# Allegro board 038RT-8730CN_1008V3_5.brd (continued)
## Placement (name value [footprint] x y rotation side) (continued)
NOREF#506  -  []  315.1 202.13 90 top
NOREF#507  -  []  321.55 225.71 0 top
NOREF#508  -  []  179.95 285.03 90 top
NOREF#509  -  []  403.66 273.64 90 top
NOREF#510  -  []  334.22 259.67 0 top
NOREF#511  -  []  327.47 196.04 0 top
NOREF#512  -  []  334.33 132.51 90 top
NOREF#513  -  []  355.48 254.44 90 top
NOREF#514  -  []  198.23 208.86 90 top
NOREF#515  -  []  404.8 268.5 0 top
NOREF#516  -  []  316.16 262.17 90 top
NOREF#517  -  []  182.03 282.65 0 top
NOREF#518  -  []  290.97 245.28 0 top
NOREF#519  -  []  289.7 269.37 90 top
NOREF#520  -  []  454.13 176.57 90 top
NOREF#521  -  []  336.14 203.74 0 top
NOREF#522  -  []  288.29 251.82 0 top
NOREF#523  -  []  283.33 205.18 0 top
NOREF#524  -  []  426.14 176.74 0 top
NOREF#525  -  []  403.98 258.4 90 top
NOREF#526  -  []  254.37 167.31 0 top
NOREF#527  -  []  372.33 265.91 0 top
NOREF#528  -  []  275.6 192.3 90 top
NOREF#529  -  []  324.75 288.95 90 top
NOREF#530  -  []  256.93 288.03 90 top
NOREF#531  -  []  347.77 116.51 90 top
NOREF#532  -  []  405.68 185.52 90 top
NOREF#533  -  []  279.47 261.29 0 top
NOREF#534  -  []  364.5 184.96 0 top
NOREF#535  -  []  208.01 210.26 90 top
NOREF#536  -  []  258.58 279.62 90 top
NOREF#537  -  []  286.82 247.81 90 top
NOREF#538  -  []  299.3 254 90 top
NOREF#539  -  []  326.58 187.88 0 top
NOREF#540  -  []  311.98 81.48 0 top
NOREF#541  -  []  332.85 167.49 90 top
NOREF#542  -  []  497.31 228.11 90 top
NOREF#543  -  []  405.7 256.05 0 top
NOREF#544  -  []  219.02 298.37 90 top
NOREF#545  -  []  289.13 251.83 90 top
NOREF#546  -  []  292.38 288.89 0 top
NOREF#547  -  []  57.77 1.56 90 top
NOREF#548  -  []  292.38 198.4 0 top
NOREF#549  -  []  294.22 256.16 90 top
NOREF#550  -  []  452.5 83.49 0 top
NOREF#551  -  []  491.79 259.74 0 top
NOREF#552  -  []  313.36 166.49 90 top
NOREF#553  -  []  288.08 255.55 0 top
NOREF#554  -  []  364.8 244.64 0 top
NOREF#555  -  []  516.65 184.97 90 top
NOREF#556  -  []  491.79 251.1 0 top
NOREF#557  -  []  496.49 381.09 0 top
NOREF#558  -  []  293.33 257.12 0 top
NOREF#559  -  []  296.44 260.67 0 top
NOREF#560  -  []  261.58 297.69 90 top
NOREF#561  -  []  307.89 167.76 0 top
NOREF#562  -  []  364.8 195.09 90 top
NOREF#563  -  []  469.09 105.96 90 top
NOREF#564  -  []  284.5 184.96 0 top
NOREF#565  -  []  452.5 86.06 0 top
NOREF#566  -  []  166.06 132.93 0 top
NOREF#567  -  []  286.9 195.41 90 top
NOREF#568  -  []  466.61 364.96 90 top
NOREF#569  -  []  361.7 209.33 0 top
NOREF#570  -  []  412.72 265.56 0 top
NOREF#571  -  []  282.3 196.5 0 top
NOREF#572  -  []  264.41 233.58 0 top
NOREF#573  -  []  497.31 220.85 90 top
NOREF#574  -  []  333.29 120.91 0 top
NOREF#575  -  []  324.8 256.37 0 top
NOREF#576  -  []  405.76 200.49 90 top
NOREF#577  -  []  190.11 292.39 90 top
NOREF#578  -  []  408.66 191.82 0 top
NOREF#579  -  []  409.86 196.29 0 top
NOREF#580  -  []  445.07 181.97 0 top
NOREF#581  -  []  182.03 274.41 90 top
NOREF#582  -  []  361.57 262.44 90 top
NOREF#583  -  []  210.19 217.5 0 top
NOREF#584  -  []  494.38 377.23 0 top
NOREF#585  -  []  319.47 263.4 0 top
NOREF#586  -  []  295.96 70.62 90 top
NOREF#587  -  []  283.63 204.65 0 top
NOREF#588  -  []  320.37 209.76 0 top
NOREF#589  -  []  375.71 71.53 90 top
NOREF#590  -  []  348.53 136.15 0 top
NOREF#591  -  []  363.77 135.5 90 top
NOREF#592  -  []  332.38 228.89 0 top
NOREF#593  -  []  330.72 359.7 90 top
NOREF#594  -  []  52.77 68.06 0 top
NOREF#595  -  []  404.8 195.09 90 top
NOREF#596  -  []  311.47 80.68 90 top
NOREF#597  -  []  214.88 360.96 90 top
NOREF#598  -  []  412.01 301.38 0 top
NOREF#599  -  []  406.35 187.8 0 top
NOREF#600  -  []  320.37 269.76 0 top
NOREF#601  -  []  368.08 195.55 0 top
NOREF#602  -  []  275.6 192.3 90 top
NOREF#603  -  []  323.98 258.4 90 top
NOREF#604  -  []  408.17 95.22 90 top
NOREF#605  -  []  294.43 263.38 90 top
NOREF#606  -  []  334.33 121.95 0 top
NOREF#607  -  []  50.8 5 0 top
NOREF#608  -  []  292.17 189.51 90 top
NOREF#609  -  []  233.84 244.55 90 top
NOREF#610  -  []  314.28 208.98 90 top
NOREF#611  -  []  352.28 261.88 0 top
NOREF#612  -  []  326.57 255.72 0 top
NOREF#613  -  []  406.3 194.08 90 top
NOREF#614  -  []  453.02 182.02 90 top
NOREF#615  -  []  314.28 268.98 90 top
NOREF#616  -  []  451.91 302.69 0 top
NOREF#617  -  []  364.48 246.16 0 top
NOREF#618  -  []  316.86 69.01 90 top
NOREF#619  -  []  409.3 251.32 90 top
NOREF#620  -  []  324.8 184.64 0 top
NOREF#621  -  []  307.44 166.16 90 top
NOREF#622  -  []  35.96 348.27 90 top
NOREF#623  -  []  480.36 198.42 0 top
NOREF#624  -  []  399.47 200.61 0 top
NOREF#625  -  []  216.24 193.01 0 top
NOREF#626  -  []  324.48 246.16 0 top
NOREF#627  -  []  340.87 216.46 90 top
NOREF#628  -  []  403.63 265.5 0 top
NOREF#629  -  []  326.29 172.14 90 top
NOREF#630  -  []  520.87 166.68 90 top
NOREF#631  -  []  175.18 251.01 90 top
NOREF#632  -  []  478.56 170.21 90 top
NOREF#633  -  []  370.32 195.4 0 top
NOREF#634  -  []  280.89 191.48 90 top
NOREF#635  -  []  237.43 266.06 0 top
NOREF#636  -  []  342.85 246 45 top
NOREF#637  -  []  327.65 84.79 90 top
NOREF#638  -  []  320.21 173.54 90 top
NOREF#639  -  []  364.18 80.76 90 top
NOREF#640  -  []  283.37 196.69 0 top
NOREF#641  -  []  511.37 301.65 0 top
NOREF#642  -  []  326.4 227.56 90 top
NOREF#643  -  []  332.33 204.49 0 top
NOREF#644  -  []  347.77 131.75 90 top
NOREF#645  -  []  242.47 292.83 90 top
NOREF#646  -  []  369.7 209.37 90 top
NOREF#647  -  []  290.97 192.03 90 top
NOREF#648  -  []  289.86 256.29 0 top
NOREF#649  -  []  517.92 216.24 0 top
NOREF#650  -  []  290.35 250.17 0 top
NOREF#651  -  []  416.14 200.99 0 top
NOREF#652  -  []  329.29 255.34 90 top
NOREF#653  -  []  453.01 295.49 0 top
NOREF#654  -  []  324.75 218.11 90 top
NOREF#655  -  []  319.47 259.92 0 top
NOREF#656  -  []  521.42 276.57 90 top
NOREF#657  -  []  421.05 295.32 0 top
NOREF#658  -  []  384.41 123.59 0 top
NOREF#659  -  []  338.02 169.36 0 top
NOREF#660  -  []  413.03 273.89 0 top
NOREF#661  -  []  368.54 191.43 0 top
NOREF#662  -  []  268.75 79.79 0 top
NOREF#663  -  []  219.44 218.9 90 top
NOREF#664  -  []  415.29 178.14 0 top
NOREF#665  -  []  52.77 6.56 0 top
NOREF#666  -  []  188.98 203 0 top
NOREF#667  -  []  334.67 251.62 90 top
NOREF#668  -  []  325.7 244.32 90 top
NOREF#669  -  []  242.32 174.51 0 top
NOREF#670  -  []  321.57 199.65 90 top
NOREF#671  -  []  321.21 252.38 0 top
NOREF#672  -  []  181.48 258.99 90 top
NOREF#673  -  []  363.13 294.52 0 top
NOREF#674  -  []  284.8 255.09 90 top
NOREF#675  -  []  507.05 334.96 0 top
NOREF#676  -  []  500.02 182.52 0 top
NOREF#677  -  []  363.61 152.59 0 top
NOREF#678  -  []  193.38 287.48 0 top
NOREF#679  -  []  433.26 348.24 0 top
NOREF#680  -  []  333.92 264.92 90 top
NOREF#681  -  []  52.77 6.56 0 top
NOREF#682  -  []  404.5 184.96 0 top
NOREF#683  -  []  415.42 259.88 90 top
NOREF#684  -  []  182.03 194.4 90 top
NOREF#685  -  []  191.18 175.97 0 top
NOREF#686  -  []  370.07 190.47 0 top
NOREF#687  -  []  210.19 191.61 0 top
NOREF#688  -  []  500.02 267 0 top
NOREF#689  -  []  365.7 207.17 0 top
NOREF#690  -  []  204.81 193.01 0 top
NOREF#691  -  []  365.3 262 0 top
NOREF#692  -  []  491.79 191.16 0 top
NOREF#693  -  []  414.43 261.87 90 top
NOREF#694  -  []  326.9 200.19 0 top
NOREF#695  -  []  333.02 256.8 0 top
NOREF#696  -  []  345.45 295.32 0 top
NOREF#697  -  []  423.36 169.36 0 top
NOREF#698  -  []  410.76 255.38 0 top
NOREF#699  -  []  328.67 195.4 90 top
NOREF#700  -  []  510.1 154.21 0 top
NOREF#701  -  []  259.15 90.74 0 top
NOREF#702  -  []  253.73 185.16 0 top
NOREF#703  -  []  373.23 266.23 0 top
NOREF#704  -  []  357.15 228.96 0 top
NOREF#705  -  []  406.58 187.42 0 top
NOREF#706  -  []  292.72 205.56 0 top
NOREF#707  -  []  337.4 96.1 0 top
NOREF#708  -  []  404.8 244.64 0 top
NOREF#709  -  []  31.6 377.83 0 top
NOREF#710  -  []  295.42 259.03 90 top
NOREF#711  -  []  511.9 245.66 90 top
NOREF#712  -  []  336.44 263.42 0 top
NOREF#713  -  []  503.22 182.52 0 top
NOREF#714  -  []  466.31 234.11 0 top
NOREF#715  -  []  287.13 84.79 90 top
NOREF#716  -  []  28.17 358.15 0 top
NOREF#717  -  []  325.7 186.14 90 top
NOREF#718  -  []  398.83 207.9 90 top
NOREF#719  -  []  251.53 212.44 0 top
NOREF#720  -  []  367.56 270 0 top
NOREF#721  -  []  465.96 232.71 0 top
NOREF#722  -  []  328.41 200.19 0 top
NOREF#723  -  []  208.01 184.61 90 top
NOREF#724  -  []  458.33 238.23 90 top
NOREF#725  -  []  400.37 203.08 0 top
NOREF#726  -  []  55.8 0 90 top
NOREF#727  -  []  318.02 79.81 0 top
NOREF#728  -  []  296.14 263.74 0 top
NOREF#729  -  []  640.8 0 90 top
NOREF#730  -  []  450.62 271.89 0 top
NOREF#731  -  []  478.8 446.5 0 top
NOREF#732  -  []  308.3 285 0 top
NOREF#733  -  []  514.57 298.46 90 top
NOREF#734  -  []  493.99 191.16 0 top
NOREF#735  -  []  370.97 252.03 90 top
NOREF#736  -  []  315.5 227.56 0 top
NOREF#737  -  []  514.57 259.77 90 top
NOREF#738  -  []  283.05 255.79 90 top
NOREF#739  -  []  253.73 274.01 0 top
NOREF#740  -  []  318.05 151.39 0 top
NOREF#741  -  []  279.47 263.4 0 top
NOREF#742  -  []  214.04 175.97 0 top
NOREF#743  -  []  338.23 89.67 0 top
NOREF#744  -  []  421.41 170.34 90 top
NOREF#745  -  []  370.97 192.03 90 top
NOREF#746  -  []  291.52 254.76 90 top
NOREF#747  -  []  491.79 267 0 top
NOREF#748  -  []  208.01 175.97 90 top
NOREF#749  -  []  471.17 382.58 0 top
NOREF#750  -  []  406.35 247.8 0 top
NOREF#751  -  []  198.23 217.5 90 top
NOREF#752  -  []  284.48 246.16 0 top
NOREF#753  -  []  366.58 200.49 90 top
NOREF#754  -  []  323.33 265.18 0 top
NOREF#755  -  []  227.42 83.32 0 top
NOREF#756  -  []  245.98 198.11 0 top
NOREF#757  -  []  300.53 204.49 0 top
NOREF#758  -  []  344.74 75.65 90 top
NOREF#759  -  []  356.8 45.5 0 top
NOREF#760  -  []  218.95 295.5 90 top
NOREF#761  -  []  327.82 269.36 90 top
NOREF#762  -  []  514.57 261.96 90 top
NOREF#763  -  []  253.3 324 0 top
NOREF#764  -  []  376.14 203.74 0 top
NOREF#765  -  []  408.09 259.55 90 top
NOREF#766  -  []  521.42 242.28 90 top
NOREF#767  -  []  471.13 208.41 0 top
NOREF#768  -  []  348.3 285 0 top
NOREF#769  -  []  321.57 198.96 90 top
NOREF#770  -  []  287.88 209.1 90 top
NOREF#771  -  []  344.47 167.76 0 top
NOREF#772  -  []  314.08 260.75 0 top
NOREF#773  -  []  27.57 380.69 90 top
NOREF#774  -  []  205.34 106.22 90 top
NOREF#775  -  []  353.33 201.92 0 top
NOREF#776  -  []  281.55 285.71 0 top
NOREF#777  -  []  363.77 118.31 90 top
NOREF#778  -  []  266.21 296.8 90 top
NOREF#779  -  []  284.1 199 0 top
NOREF#780  -  []  488.59 263.8 90 top
NOREF#781  -  []  317.29 137.95 0 top
NOREF#782  -  []  225.47 295.88 0 top
NOREF#783  -  []  367.93 244.02 90 top
NOREF#784  -  []  369.3 191.32 90 top
NOREF#785  -  []  366.35 247.8 0 top
NOREF#786  -  []  262.58 350.14 0 top
NOREF#787  -  []  243.59 208.8 90 top
NOREF#788  -  []  333.02 197.65 0 top
NOREF#789  -  []  420.81 266.84 90 top
NOREF#790  -  []  373.36 190.09 0 top
NOREF#791  -  []  260.06 383.9 90 top
NOREF#792  -  []  466.31 286.79 0 top
NOREF#793  -  []  452.86 93.57 90 top
NOREF#794  -  []  409.71 195.72 90 top
NOREF#795  -  []  413.3 197.5 90 top
NOREF#796  -  []  315.6 252.3 90 top
NOREF#797  -  []  514.57 241.31 90 top
NOREF#798  -  []  323.33 204.33 0 top
NOREF#799  -  []  33.88 370.85 0 top
NOREF#800  -  []  450.39 84.76 0 top
NOREF#801  -  []  366.23 247.42 0 top
NOREF#802  -  []  414.73 172.88 0 top
NOREF#803  -  []  409.35 210.01 0 top
NOREF#804  -  []  520.87 246.69 90 top
NOREF#805  -  []  349.3 246 90 top
NOREF#806  -  []  349.18 256.09 90 top
NOREF#807  -  []  383.3 220 0 top
NOREF#808  -  []  188.31 191.57 90 top
NOREF#809  -  []  380.3 197 90 top
NOREF#810  -  []  389.18 258.29 90 top
NOREF#811  -  []  369.13 251.83 90 top
NOREF#812  -  []  221.09 167.31 90 top
NOREF#813  -  []  313.93 102.82 0 top
NOREF#814  -  []  365.68 245.52 90 top
NOREF#815  -  []  289.11 191.32 90 top
NOREF#816  -  []  232.16 300.68 0 top
NOREF#817  -  []  364.54 212.7 90 top
NOREF#818  -  []  293.23 267.72 0 top
NOREF#819  -  []  516.65 207.83 90 top
NOREF#820  -  []  333.03 273.89 0 top
NOREF#821  -  []  277 290.7 90 top
NOREF#822  -  []  408.89 251.89 0 top
NOREF#823  -  []  293.23 264.02 0 top
NOREF#824  -  []  211.84 168.71 0 top
NOREF#825  -  []  326.08 200.19 0 top
NOREF#826  -  []  465.73 208.41 0 top
NOREF#827  -  []  521.42 162.27 90 top
NOREF#828  -  []  331.55 189.53 90 top
NOREF#829  -  []  282.3 196.5 0 top
NOREF#830  -  []  339.43 227.49 90 top
NOREF#831  -  []  374.43 201.87 90 top
NOREF#832  -  []  557.05 87.46 0 top
NOREF#833  -  []  289.66 255.8 90 top
NOREF#834  -  []  429.34 176.74 0 top
NOREF#835  -  []  405.1 254.72 0 top
NOREF#836  -  []  413.23 266.23 0 top
NOREF#837  -  []  188.98 175.97 0 top
NOREF#838  -  []  406.29 172.14 90 top
NOREF#839  -  []  494.38 379.8 0 top
NOREF#840  -  []  253.73 288.03 0 top
NOREF#841  -  []  240.78 254.09 0 top
NOREF#842  -  []  405.98 247.8 0 top
NOREF#843  -  []  195.73 224.34 90 top
NOREF#844  -  []  414.57 218.11 90 top
NOREF#845  -  []  511.37 175.92 0 top
NOREF#846  -  []  409.7 176.75 0 top
NOREF#847  -  []  414.22 260.52 0 top
NOREF#848  -  []  245.98 266.69 0 top
NOREF#849  -  []  489.17 295.43 0 top
NOREF#850  -  []  288.5 210.01 0 top
NOREF#851  -  []  220.09 291.05 90 top
NOREF#852  -  []  24.62 412.09 90 top
NOREF#853  -  []  215.43 367.16 90 top
NOREF#854  -  []  332.72 265.56 0 top
NOREF#855  -  []  500.56 80.76 90 top
NOREF#856  -  []  430.7 167.76 0 top
NOREF#857  -  []  368.89 191.43 0 top
NOREF#858  -  []  376.63 169.36 0 top
NOREF#859  -  []  198.23 201.6 90 top
NOREF#860  -  []  277.15 228.96 0 top
NOREF#861  -  []  273.3 180 90 top
NOREF#862  -  []  404.8 247.74 90 top
NOREF#863  -  []  294.22 197.01 90 top
NOREF#864  -  []  181.48 293.28 90 top
NOREF#865  -  []  401.57 201.78 90 top
NOREF#866  -  []  414.22 197.01 90 top
NOREF#867  -  []  325.97 193.75 0 top
NOREF#868  -  []  276.62 97.42 90 top
NOREF#869  -  []  274.28 268.98 90 top
NOREF#870  -  []  322.9 269.33 0 top
NOREF#871  -  []  292.7 250.29 0 top
NOREF#872  -  []  228.44 278.84 0 top
NOREF#873  -  []  321.8 297.54 0 top
NOREF#874  -  []  374.43 203.38 90 top
NOREF#875  -  []  513.7 222.79 90 top
NOREF#876  -  []  211.84 193.01 0 top
NOREF#877  -  []  282.2 269.75 0 top
NOREF#878  -  []  271.3 222 0 top
NOREF#879  -  []  326.8 247.3 90 top
NOREF#880  -  []  192.73 292.39 0 top
NOREF#881  -  []  218.13 108.35 90 top
NOREF#882  -  []  331.05 276.46 90 top
NOREF#883  -  []  414.57 282.51 90 top
NOREF#884  -  []  368.24 298.51 90 top
NOREF#885  -  []  175.18 171 90 top
NOREF#886  -  []  521.42 293.5 0 top
NOREF#887  -  []  408.46 196.44 0 top
NOREF#888  -  []  330.67 191.75 90 top
NOREF#889  -  []  326.82 187.81 90 top
NOREF#890  -  []  414.12 294.95 0 top
NOREF#891  -  []  421.41 167.75 90 top
NOREF#892  -  []  364.8 255.09 90 top
NOREF#893  -  []  336.24 259.17 0 top
NOREF#894  -  []  276.1 286.51 0 top
NOREF#895  -  []  363.33 204.33 0 top
NOREF#896  -  []  206.37 333.52 0 top
NOREF#897  -  []  471.13 216.81 0 top
NOREF#898  -  []  319.69 298.81 0 top
NOREF#899  -  []  286.4 287.55 90 top
NOREF#900  -  []  328.76 209.36 90 top
NOREF#901  -  []  414.11 88.62 0 top
NOREF#902  -  []  520.87 200.97 90 top
NOREF#903  -  []  376.44 260.67 0 top
NOREF#904  -  []  381.05 295.32 0 top
NOREF#905  -  []  319.09 137.19 0 top
NOREF#906  -  []  409.34 186.99 0 top
NOREF#907  -  []  356.16 202.17 90 top
NOREF#908  -  []  407.88 209.1 90 top
NOREF#909  -  []  403.33 204.33 0 top
NOREF#910  -  []  375.71 72.8 90 top
NOREF#911  -  []  198.61 118.51 0 top
NOREF#912  -  []  413.83 246.93 0 top
NOREF#913  -  []  209.66 167.31 90 top
NOREF#914  -  []  50.8 465 0 top
NOREF#915  -  []  400.37 260.29 0 top
NOREF#916  -  []  289.3 191.32 90 top
NOREF#917  -  []  200.41 193.01 0 top
NOREF#918  -  []  403.98 259.6 90 top
NOREF#919  -  []  293.23 202.51 0 top
NOREF#920  -  []  284.75 220.31 90 top
NOREF#921  -  []  516.65 191.02 0 top
NOREF#922  -  []  364.1 199 0 top
NOREF#923  -  []  409.66 195.8 90 top
NOREF#924  -  []  332.19 192 90 top
NOREF#925  -  []  351.84 169.66 0 top
NOREF#926  -  []  516.65 242.12 90 top
NOREF#927  -  []  287.36 200.49 90 top
NOREF#928  -  []  281.8 300.11 0 top
NOREF#929  -  []  405.7 267.17 0 top
NOREF#930  -  []  226.93 241.49 90 top
NOREF#931  -  []  282.56 83.49 0 top
NOREF#932  -  []  482.56 216.81 0 top
NOREF#933  -  []  404.75 282.51 90 top
NOREF#934  -  []  369.61 259.55 90 top
NOREF#935  -  []  496.49 381.09 0 top
NOREF#936  -  []  309.18 258.29 90 top
NOREF#937  -  []  187.33 217.5 0 top
NOREF#938  -  []  326.33 195.34 90 top
NOREF#939  -  []  224.59 243.15 0 top
NOREF#940  -  []  462.76 263.8 90 top
NOREF#941  -  []  -18.78 412.09 0 top
NOREF#942  -  []  482.91 220.85 90 top
NOREF#943  -  []  451.91 192.56 0 top
NOREF#944  -  []  188.98 271.58 0 top
NOREF#945  -  []  279.47 210.08 0 top
NOREF#946  -  []  409.3 251.52 90 top
NOREF#947  -  []  238.62 264.79 0 top
NOREF#948  -  []  309.18 260.49 90 top
NOREF#949  -  []  328.09 255.99 0 top
NOREF#950  -  []  391.08 208.98 0 top
NOREF#951  -  []  440.51 229.39 90 top
NOREF#952  -  []  369.77 192.68 0 top
NOREF#953  -  []  288.3 265 0 top
NOREF#954  -  []  182.03 191.21 90 top
NOREF#955  -  []  383.61 122.32 0 top
NOREF#956  -  []  244.11 263.52 90 top
NOREF#957  -  []  216.24 218.9 0 top
NOREF#958  -  []  305.76 344.61 90 top
NOREF#959  -  []  290.97 190.15 0 top
NOREF#960  -  []  505.92 222.45 0 top
NOREF#961  -  []  246.78 226.6 0 top
NOREF#962  -  []  239.54 230.5 0 top
NOREF#963  -  []  221.09 251.79 90 top
NOREF#964  -  []  412.33 207.4 0 top
NOREF#965  -  []  294.73 170.29 0 top
NOREF#966  -  []  477.16 247.91 90 top
NOREF#967  -  []  516.65 253.55 90 top
NOREF#968  -  []  359.47 270.08 0 top
NOREF#969  -  []  229.35 382.58 90 top
NOREF#970  -  []  333.32 197.97 0 top
NOREF#971  -  []  364.81 121.95 0 top
NOREF#972  -  []  337.33 87.58 0 top
NOREF#973  -  []  360.37 200.97 0 top
NOREF#974  -  []  385.98 263.69 0 top
NOREF#975  -  []  281.7 269.33 0 top
NOREF#976  -  []  309.18 196.09 90 top
NOREF#977  -  []  200.41 271.58 0 top
NOREF#978  -  []  319.69 301.38 0 top
NOREF#979  -  []  389.34 243.1 0 top
NOREF#980  -  []  326.82 247.81 90 top
NOREF#981  -  []  334.5 189.29 90 top
NOREF#982  -  []  57.77 1.56 90 top
NOREF#983  -  []  269.18 200.49 90 top
NOREF#984  -  []  333.13 147.59 90 top
NOREF#985  -  []  52.77 6.56 0 top
NOREF#986  -  []  246.78 295.18 0 top
NOREF#987  -  []  328.67 255.4 90 top
NOREF#988  -  []  477.16 232.71 0 top
NOREF#989  -  []  320.37 260.29 0 top
NOREF#990  -  []  514.57 227.67 90 top
NOREF#991  -  []  175.18 182.43 90 top
NOREF#992  -  []  520.17 212.21 90 top
NOREF#993  -  []  329.86 256.29 0 top
NOREF#994  -  []  373.23 264.02 0 top
NOREF#995  -  []  431.03 189.48 0 top
NOREF#996  -  []  404.8 246.46 0 top
NOREF#997  -  []  155.68 219.47 0 top
NOREF#998  -  []  286.9 256.05 90 top
NOREF#999  -  []  286.37 293.68 90 top
NOREF#1000  -  []  336.48 126.78 90 top
NOREF#1001  -  []  369.29 195.34 90 top
NOREF#1002  -  []  406.3 193.44 90 top
NOREF#1003  -  []  468.93 251.1 0 top
NOREF#1004  -  []  457.37 381.09 0 top
NOREF#1005  -  []  353.3 290 0 top
NOREF#1006  -  []  200.41 253.19 0 top
NOREF#1007  -  []  326.99 247.5 90 top
NOREF#1008  -  []  500.02 247.91 90 top
NOREF#1009  -  []  179.95 302.51 0 top
NOREF#1010  -  []  367.08 257.69 0 top
NOREF#1011  -  []  213.15 378.53 0 top
NOREF#1012  -  []  461.95 377.26 90 top
NOREF#1013  -  []  282.04 74.78 0 top
NOREF#1014  -  []  368.46 196.44 0 top
NOREF#1015  -  []  288.09 260.49 90 top
NOREF#1016  -  []  368.07 193.43 90 top
NOREF#1017  -  []  439.67 291.85 0 top
NOREF#1018  -  []  347.77 137.95 0 top
NOREF#1019  -  []  289.82 246.49 0 top
NOREF#1020  -  []  361.55 228.96 0 top
NOREF#1021  -  []  292.17 244.64 90 top
NOREF#1022  -  []  204.81 175.97 0 top
NOREF#1023  -  []  369.67 269.11 90 top
NOREF#1024  -  []  405.76 260.49 90 top
NOREF#1025  -  []  330.97 252.03 90 top
NOREF#1026  -  []  186.51 292.39 0 top
NOREF#1027  -  []  505.92 302.46 0 top
NOREF#1028  -  []  175.18 205.29 90 top
NOREF#1029  -  []  381.07 138.01 0 top
NOREF#1030  -  []  363.33 264.33 0 top
NOREF#1031  -  []  288.89 191.89 0 top
NOREF#1032  -  []  369.61 199.55 90 top
NOREF#1033  -  []  262.58 335.72 0 top
NOREF#1034  -  []  363.34 273.34 0 top
NOREF#1035  -  []  364.8 245.52 0 top
NOREF#1036  -  []  482.91 255.14 90 top
NOREF#1037  -  []  219.02 229.79 90 top
NOREF#1038  -  []  356.79 294.51 0 top
NOREF#1039  -  []  411.14 185.99 90 top
NOREF#1040  -  []  211.84 271.58 0 top
NOREF#1041  -  []  363.05 195.79 90 top
NOREF#1042  -  []  406.94 209.1 90 top
NOREF#1043  -  []  287.59 256.03 0 top
NOREF#1044  -  []  500.02 222.25 90 top
NOREF#1045  -  []  374.22 256.16 90 top
NOREF#1046  -  []  212.27 298.04 0 top
NOREF#1047  -  []  275.93 267.58 90 top
NOREF#1048  -  []  52.77 405.06 0 top
NOREF#1049  -  []  155.68 265.19 0 top
NOREF#1050  -  []  369.86 256.29 0 top
NOREF#1051  -  []  246.78 260.89 0 top
NOREF#1052  -  []  323.07 83.49 0 top
NOREF#1053  -  []  221.62 217.5 0 top
NOREF#1054  -  []  328.09 260.49 90 top
NOREF#1055  -  []  503.22 216.81 0 top
NOREF#1056  -  []  355.6 192.3 90 top
NOREF#1057  -  []  462.76 301.29 0 top
NOREF#1058  -  []  355.93 207.58 90 top
NOREF#1059  -  []  286.3 194.08 90 top
NOREF#1060  -  []  327.65 87.35 90 top
NOREF#1061  -  []  208.01 244.55 90 top
NOREF#1062  -  []  283.05 195.79 90 top
NOREF#1063  -  []  175.18 239.58 90 top
NOREF#1064  -  []  429.69 187.88 90 top
NOREF#1065  -  []  412.72 205.56 0 top
NOREF#1066  -  []  493.99 294.03 0 top
NOREF#1067  -  []  253.99 305.54 0 top
NOREF#1068  -  []  330.32 255.4 0 top
NOREF#1069  -  []  195.27 118.51 0 top
NOREF#1070  -  []  216.24 184.61 0 top
NOREF#1071  -  []  368.76 209.36 90 top
NOREF#1072  -  []  477.16 259.74 0 top
NOREF#1073  -  []  408.53 287.49 0 top
NOREF#1074  -  []  491.79 216.81 0 top
NOREF#1075  -  []  480.36 276.99 0 top
NOREF#1076  -  []  396.25 297.68 90 top
NOREF#1077  -  []  414.42 264.17 90 top
NOREF#1078  -  []  400.35 208.16 90 top
NOREF#1079  -  []  450.62 237.6 0 top
NOREF#1080  -  []  500.02 301.29 0 top
NOREF#1081  -  []  427.3 136.36 0 top
NOREF#1082  -  []  480.36 216.81 0 top
NOREF#1083  -  []  363.61 117.11 90 top
NOREF#1084  -  []  416.44 260.67 0 top
NOREF#1085  -  []  188.98 218.9 0 top
NOREF#1086  -  []  214.04 244.55 0 top
NOREF#1087  -  []  385.45 295.32 0 top
NOREF#1088  -  []  466.31 218.21 0 top
NOREF#1089  -  []  284.8 255.09 90 top
NOREF#1090  -  []  240.95 223.95 0 top
NOREF#1091  -  []  326.13 245.02 0 top
NOREF#1092  -  []  368.56 254.22 0 top
NOREF#1093  -  []  266.68 208.98 0 top
NOREF#1094  -  []  331.82 265.24 0 top
NOREF#1095  -  []  366.35 187.8 0 top
NOREF#1096  -  []  363.77 148.79 90 top
NOREF#1097  -  []  408.89 191.43 0 top
NOREF#1098  -  []  289.08 127.05 90 top
NOREF#1099  -  []  275.6 300.87 0 top
NOREF#1100  -  []  328.28 257.05 90 top
NOREF#1101  -  []  283.59 97.42 90 top
NOREF#1102  -  []  280.37 263.08 0 top
NOREF#1103  -  []  330.97 185.28 0 top
NOREF#1104  -  []  329.87 256.73 0 top
NOREF#1105  -  []  26.52 339.1 0 top
NOREF#1106  -  []  175.18 262.44 90 top
NOREF#1107  -  []  328.28 197.05 90 top
NOREF#1108  -  []  366.3 253.44 90 top
NOREF#1109  -  []  55.8 0 90 top
NOREF#1110  -  []  369.13 191.83 90 top
NOREF#1111  -  []  238.16 263.19 90 top
NOREF#1112  -  []  372.38 198.4 0 top
NOREF#1113  -  []  361.57 202.44 90 top
NOREF#1114  -  []  279.47 200.61 0 top
NOREF#1115  -  []  485.88 212.21 90 top
NOREF#1116  -  []  414.67 191.62 90 top
NOREF#1117  -  []  328.89 251.43 0 top
NOREF#1118  -  []  297.34 263.1 90 top
NOREF#1119  -  []  465.73 247.91 90 top
NOREF#1120  -  []  375.29 178.14 0 top
NOREF#1121  -  []  404.1 259 0 top
NOREF#1122  -  []  222.8 45.5 0 top
NOREF#1123  -  []  439.67 247.35 90 top
NOREF#1124  -  []  285.13 188.64 0 top
NOREF#1125  -  []  249.33 212.44 0 top
NOREF#1126  -  []  332.33 207.4 0 top
NOREF#1127  -  []  505.92 188.16 0 top
NOREF#1128  -  []  328.09 200.49 90 top
NOREF#1129  -  []  347.24 75.38 90 top
NOREF#1130  -  []  329.31 191.57 90 top
NOREF#1131  -  []  230.64 210.26 0 top
NOREF#1132  -  []  282.9 369.19 0 top
NOREF#1133  -  []  366.99 187.5 90 top
NOREF#1134  -  []  288.1 259.55 90 top
NOREF#1135  -  []  482.91 289.43 90 top
NOREF#1136  -  []  50.8 5 0 top
NOREF#1137  -  []  320.35 268.16 90 top
NOREF#1138  -  []  332.19 252 90 top
NOREF#1139  -  []  339.37 97.97 0 top
NOREF#1140  -  []  493.99 174.12 0 top
NOREF#1141  -  []  488.59 191.16 0 top
NOREF#1142  -  []  295.13 272.93 90 top
NOREF#1143  -  []  208.01 227.3 90 top
NOREF#1144  -  []  182.03 202.64 0 top
NOREF#1145  -  []  287.82 269.36 90 top
NOREF#1146  -  []  355.48 194.44 90 top
NOREF#1147  -  []  505.42 191.16 0 top
NOREF#1148  -  []  256.93 212.44 90 top
NOREF#1149  -  []  491.79 182.52 0 top
NOREF#1150  -  []  50.8 465 0 top
NOREF#1151  -  []  414.22 200.52 0 top
NOREF#1152  -  []  364.8 187.74 90 top
NOREF#1153  -  []  507.47 188.5 90 top
NOREF#1154  -  []  336.28 121.95 0 top
NOREF#1155  -  []  202.61 218.9 0 top
NOREF#1156  -  []  263.3 280 0 top
NOREF#1157  -  []  296.14 200.99 0 top
NOREF#1158  -  []  243.59 243.09 90 top
NOREF#1159  -  []  286.33 195.34 90 top
NOREF#1160  -  []  465.73 216.81 0 top
NOREF#1161  -  []  476.96 97.33 90 top
NOREF#1162  -  []  320.21 169.14 90 top
NOREF#1163  -  []  230.87 287.48 90 top
NOREF#1164  -  []  365.2 77.1 0 top
NOREF#1165  -  []  368.41 200.19 0 top
NOREF#1166  -  []  373.02 197.65 0 top
NOREF#1167  -  []  198.76 277.44 0 top
NOREF#1168  -  []  333.47 252.26 0 top
NOREF#1169  -  []  321.55 288.95 0 top
NOREF#1170  -  []  187.11 224.34 0 top
NOREF#1171  -  []  333.32 199.35 0 top
NOREF#1172  -  []  439.67 216.26 0 top
NOREF#1173  -  []  286.62 270 0 top
NOREF#1174  -  []  274.08 200.75 0 top
NOREF#1175  -  []  334.43 204.17 90 top
NOREF#1176  -  []  493.99 225.45 0 top
NOREF#1177  -  []  323.66 213.64 90 top
NOREF#1178  -  []  408.08 255.55 0 top
NOREF#1179  -  []  288.46 196.44 0 top
NOREF#1180  -  []  488.59 229.51 90 top
NOREF#1181  -  []  450.39 228.51 90 top
NOREF#1182  -  []  375.42 199.88 90 top
NOREF#1183  -  []  311.08 268.98 0 top
NOREF#1184  -  []  401.57 200.33 90 top
NOREF#1185  -  []  407.36 260.49 90 top
NOREF#1186  -  []  370.97 185.28 0 top
NOREF#1187  -  []  285.3 267 90 top
NOREF#1188  -  []  434.35 278.29 90 top
NOREF#1189  -  []  179.95 211.07 0 top
NOREF#1190  -  []  410.3 263 90 top
NOREF#1191  -  []  316.86 75.11 90 top
NOREF#1192  -  []  227.67 261.59 0 top
NOREF#1193  -  []  216.24 261.59 0 top
NOREF#1194  -  []  291.37 285.71 0 top
NOREF#1195  -  []  214.04 271.58 0 top
NOREF#1196  -  []  326.58 247.88 0 top
NOREF#1197  -  []  291.55 249.53 90 top
NOREF#1198  -  []  461.95 377.26 90 top
NOREF#1199  -  []  179.95 182.16 90 top
NOREF#1200  -  []  337.34 204.47 90 top
NOREF#1201  -  []  55.8 0 90 top
NOREF#1202  -  []  334.5 249.29 90 top
NOREF#1203  -  []  367 247.55 90 top
NOREF#1204  -  []  325.7 256.05 0 top
NOREF#1205  -  []  366.3 193.44 90 top
NOREF#1206  -  []  503.22 294.03 0 top
NOREF#1207  -  []  416.84 171.61 0 top
NOREF#1208  -  []  508.74 238.1 90 top
NOREF#1209  -  []  351.72 142.02 90 top
NOREF#1210  -  []  231.15 359.7 90 top
NOREF#1211  -  []  368.67 195.4 90 top
NOREF#1212  -  []  399.47 270.08 0 top
NOREF#1213  -  []  429.81 167.76 0 top
NOREF#1214  -  []  283.63 264.65 0 top
NOREF#1215  -  []  405.13 248.64 0 top
NOREF#1216  -  []  426.14 183.1 0 top
NOREF#1217  -  []  329.61 199.55 90 top
NOREF#1218  -  []  268.3 225 0 top
NOREF#1219  -  []  364.8 247.74 90 top
NOREF#1220  -  []  293.33 259.35 0 top
NOREF#1221  -  []  354.08 260.75 0 top
NOREF#1222  -  []  505.73 361.76 90 top
NOREF#1223  -  []  285.13 248.64 0 top
NOREF#1224  -  []  406.9 195.41 90 top
NOREF#1225  -  []  368.28 197.05 90 top
NOREF#1226  -  []  482.91 296.69 90 top
NOREF#1227  -  []  520.17 280.79 90 top
NOREF#1228  -  []  315.93 267.58 90 top
NOREF#1229  -  []  290.76 255.38 0 top
NOREF#1230  -  []  521.42 253.71 90 top
NOREF#1231  -  []  355.33 296.48 90 top
NOREF#1232  -  []  422.85 246 45 top
NOREF#1233  -  []  364.8 196.37 0 top
NOREF#1234  -  []  220.09 222.47 90 top
NOREF#1235  -  []  366.96 126.78 90 top
NOREF#1236  -  []  465.73 182.52 0 top
NOREF#1237  -  []  379.2 167.5 90 top
NOREF#1238  -  []  57.77 1.56 90 top
NOREF#1239  -  []  514.57 181.95 90 top
NOREF#1240  -  []  410.9 262.85 90 top
NOREF#1241  -  []  287.56 210 0 top
NOREF#1242  -  []  386.5 93.18 0 top
NOREF#1243  -  []  497.31 272.39 90 top
NOREF#1244  -  []  497.31 193.82 90 top
NOREF#1245  -  []  516.65 225.31 0 top
NOREF#1246  -  []  314.45 360.96 90 top
NOREF#1247  -  []  326.37 293.68 90 top
NOREF#1248  -  []  221.62 225.9 0 top
NOREF#1249  -  []  462.76 222.25 90 top
NOREF#1250  -  []  326.62 210 0 top
NOREF#1251  -  []  278.83 267.9 90 top
NOREF#1252  -  []  317.15 288.95 0 top
NOREF#1253  -  []  380.81 266.84 90 top
NOREF#1254  -  []  362.41 191.74 90 top
NOREF#1255  -  []  383.3 190 90 top
NOREF#1256  -  []  232.52 217.5 90 top
NOREF#1257  -  []  399.47 199.92 0 top
NOREF#1258  -  []  488.59 239.5 90 top
NOREF#1259  -  []  380.3 257 90 top
NOREF#1260  -  []  397.15 288.95 0 top
NOREF#1261  -  []  414.47 93.57 90 top
NOREF#1262  -  []  445.07 188.98 0 top
NOREF#1263  -  []  202.61 295.88 0 top
NOREF#1264  -  []  406.3 254.08 90 top
NOREF#1265  -  []  428.82 286.24 0 top
NOREF#1266  -  []  270.8 45.5 0 top
NOREF#1267  -  []  435.12 225.37 90 top
NOREF#1268  -  []  513.7 154.21 90 top
NOREF#1269  -  []  404.54 272.7 90 top
NOREF#1270  -  []  333.29 135.5 90 top
NOREF#1271  -  []  294.43 267.08 90 top
NOREF#1272  -  []  221.62 260.19 0 top
NOREF#1273  -  []  282.9 269.33 0 top
NOREF#1274  -  []  459.51 199.5 90 top
NOREF#1275  -  []  335.13 272.93 90 top
NOREF#1276  -  []  279.69 298.81 0 top
NOREF#1277  -  []  465.96 259.74 0 top
NOREF#1278  -  []  477.16 195.22 90 top
NOREF#1279  -  []  405.3 267 90 top
NOREF#1280  -  []  367.47 196.04 0 top
NOREF#1281  -  []  372.33 202.19 0 top
NOREF#1282  -  []  188.31 294.44 90 top
NOREF#1283  -  []  273.27 83.52 90 top
NOREF#1284  -  []  496.49 378.53 0 top
NOREF#1285  -  []  468.93 208.41 0 top
NOREF#1286  -  []  198.76 251.79 0 top
NOREF#1287  -  []  288.82 269.11 90 top
NOREF#1288  -  []  256.93 253.74 90 top
NOREF#1289  -  []  471.13 251.1 0 top
NOREF#1290  -  []  333.3 197.5 90 top
NOREF#1291  -  []  283.34 213.34 0 top
NOREF#1292  -  []  369.86 196.29 0 top
NOREF#1293  -  []  408.09 195.99 0 top
NOREF#1294  -  []  373.23 204.81 0 top
NOREF#1295  -  []  330.97 192.03 90 top
NOREF#1296  -  []  286.99 187.3 90 top
NOREF#1297  -  []  337.34 260.35 90 top
NOREF#1298  -  []  349.57 137.19 0 top
NOREF#1299  -  []  480.36 294.03 0 top
NOREF#1300  -  []  327.45 194.68 90 top
NOREF#1301  -  []  327.08 197.69 0 top
NOREF#1302  -  []  353.74 69.49 0 top
NOREF#1303  -  []  325.97 253.75 0 top
NOREF#1304  -  []  354.08 200.75 0 top
NOREF#1305  -  []  347.77 122.71 0 top
NOREF#1306  -  []  311.54 176.74 0 top
NOREF#1307  -  []  211.2 226.28 0 top
NOREF#1308  -  []  422.85 186 45 top
NOREF#1309  -  []  365.92 226.51 0 top
NOREF#1310  -  []  455.27 379.8 0 top
NOREF#1311  -  []  449.82 174.82 0 top
NOREF#1312  -  []  517.92 204.81 0 top
NOREF#1313  -  []  433.44 127.05 90 top
NOREF#1314  -  []  373.92 204.92 90 top
NOREF#1315  -  []  516.65 305.32 0 top
NOREF#1316  -  []  258.58 169.74 90 top
NOREF#1317  -  []  361.57 200.33 90 top
NOREF#1318  -  []  477.16 187.96 90 top
NOREF#1319  -  []  291.88 260.12 90 top
NOREF#1320  -  []  329.82 246.49 0 top
NOREF#1321  -  []  294.57 222.51 90 top
NOREF#1322  -  []  370.99 192.65 0 top
NOREF#1323  -  []  477.74 175.52 0 top
NOREF#1324  -  []  319.35 288.95 0 top
NOREF#1325  -  []  273.3 230 0 top
NOREF#1326  -  []  332.33 203.7 0 top
NOREF#1327  -  []  355.41 75.65 90 top
NOREF#1328  -  []  485.88 203.81 90 top
NOREF#1329  -  []  319.47 199.92 0 top
NOREF#1330  -  []  482.91 262.4 90 top
NOREF#1331  -  []  332.53 146.99 90 top
NOREF#1332  -  []  215.43 361.76 90 top
NOREF#1333  -  []  477.16 182.52 0 top
NOREF#1334  -  []  327.47 256.04 0 top
NOREF#1335  -  []  280.89 251.48 90 top
NOREF#1336  -  []  315.48 194.44 90 top
NOREF#1337  -  []  370.67 251.75 90 top
NOREF#1338  -  []  332.9 171.35 90 top
NOREF#1339  -  []  416.14 260.99 0 top
NOREF#1340  -  []  429 282.55 0 top
NOREF#1341  -  []  282.56 88.62 0 top
NOREF#1342  -  []  190.11 189.52 90 top
NOREF#1343  -  []  372.9 171.35 90 top
NOREF#1344  -  []  369.31 251.57 90 top
NOREF#1345  -  []  329.11 251.32 90 top
NOREF#1346  -  []  327.38 258.01 0 top
NOREF#1347  -  []  269.3 283 0 top
NOREF#1348  -  []  416.84 171.61 0 top
NOREF#1349  -  []  287.56 270 0 top
NOREF#1350  -  []  283.63 205.5 0 top
NOREF#1351  -  []  321.96 367.16 90 top
NOREF#1352  -  []  395.6 217.7 0 top
NOREF#1353  -  []  365.7 196.05 0 top
NOREF#1354  -  []  363.63 204.65 0 top
NOREF#1355  -  []  488.59 301.29 0 top
NOREF#1356  -  []  296.8 259 90 top
NOREF#1357  -  []  415.92 176.25 90 top
NOREF#1358  -  []  516.65 276.41 90 top
NOREF#1359  -  []  179.95 245.36 0 top
NOREF#1360  -  []  391.3 188 90 top
NOREF#1361  -  []  286.37 298.84 90 top
NOREF#1362  -  []  327.56 210 0 top
NOREF#1363  -  []  408.08 195.55 0 top
NOREF#1364  -  []  211.78 99.27 0 top
NOREF#1365  -  []  505.92 268.17 0 top
NOREF#1366  -  []  432.75 279.63 90 top
NOREF#1367  -  []  359.7 301.38 0 top
NOREF#1368  -  []  332.7 190.29 0 top
NOREF#1369  -  []  408.3 265 0 top
NOREF#1370  -  []  336.14 260.99 0 top
NOREF#1371  -  []  269.13 298.07 90 top
NOREF#1372  -  []  198.23 183.21 90 top
NOREF#1373  -  []  175.18 285.3 90 top
NOREF#1374  -  []  449.82 209.11 0 top
NOREF#1375  -  []  514.57 170.52 90 top
NOREF#1376  -  []  175.18 193.86 90 top
NOREF#1377  -  []  284.1 199 90 top
NOREF#1378  -  []  480.36 259.74 0 top
NOREF#1379  -  []  321.24 126.78 90 top
NOREF#1380  -  []  432.75 295.48 90 top
NOREF#1381  -  []  273.04 75.63 0 top
NOREF#1382  -  []  271.08 208.98 0 top
NOREF#1383  -  []  297.78 228.89 90 top
NOREF#1384  -  []  238.16 297.48 90 top
NOREF#1385  -  []  368.3 265 0 top
NOREF#1386  -  []  370.3 203 90 top
NOREF#1387  -  []  221.62 251.79 0 top
NOREF#1388  -  []  482.56 294.03 0 top
NOREF#1389  -  []  451.91 268.4 0 top
NOREF#1390  -  []  485.88 280.79 90 top
NOREF#1391  -  []  282.3 209.2 0 top
NOREF#1392  -  []  404.8 256.37 0 top
NOREF#1393  -  []  187.33 174.57 0 top
NOREF#1394  -  []  312.28 73.33 0 top
NOREF#1395  -  []  410.62 193.99 90 top
NOREF#1396  -  []  403.61 82 0 top
NOREF#1397  -  []  376.84 171.61 0 top
NOREF#1398  -  []  52.77 405.06 0 top
NOREF#1399  -  []  333.29 150.74 90 top
NOREF#1400  -  []  324.5 244.96 0 top
NOREF#1401  -  []  466.31 261.14 0 top
NOREF#1402  -  []  348.37 152.59 0 top
NOREF#1403  -  []  521.42 167.77 0 top
NOREF#1404  -  []  332.33 262.19 0 top
NOREF#1405  -  []  179.95 199.64 0 top
NOREF#1406  -  []  273.27 83.52 90 top
NOREF#1407  -  []  474.02 87.9 0 top
NOREF#1408  -  []  204.8 23.5 90 top
NOREF#1409  -  []  367.68 260.19 0 top
NOREF#1410  -  []  285.7 256.05 0 top
NOREF#1411  -  []  338.23 89.67 90 top
NOREF#1412  -  []  326.35 247.8 0 top
NOREF#1413  -  []  500.02 298.09 90 top
NOREF#1414  -  []  303.25 295.32 0 top
NOREF#1415  -  []  373.3 197.5 90 top
NOREF#1416  -  []  372.08 210.01 0 top
NOREF#1417  -  []  520.17 220.85 90 top
NOREF#1418  -  []  50.8 465 0 top
NOREF#1419  -  []  282.56 86.06 0 top
NOREF#1420  -  []  286.3 254.08 90 top
NOREF#1421  -  []  333.23 204.02 0 top
NOREF#1422  -  []  283.98 199.6 90 top
NOREF#1423  -  []  326.33 187.99 90 top
NOREF#1424  -  []  308.78 167.76 0 top
NOREF#1425  -  []  301.41 172.91 90 top
NOREF#1426  -  []  263.3 190 90 top
NOREF#1427  -  []  390.44 169.66 0 top
NOREF#1428  -  []  366.82 187.81 90 top
NOREF#1429  -  []  287 187.28 90 top
NOREF#1430  -  []  195.73 292.92 90 top
NOREF#1431  -  []  368.5 210.01 0 top
NOREF#1432  -  []  367.28 259.55 90 top
NOREF#1433  -  []  389.34 183.1 0 top
NOREF#1434  -  []  500.02 187.96 90 top
NOREF#1435  -  []  288.88 199.55 90 top
NOREF#1436  -  []  364.75 288.95 90 top
NOREF#1437  -  []  458.44 275.39 90 top
NOREF#1438  -  []  361.57 201.78 90 top
NOREF#1439  -  []  326.3 267 0 top
NOREF#1440  -  []  281.57 262.44 90 top
NOREF#1441  -  []  28.84 362.2 0 top
NOREF#1442  -  []  413.28 209.37 90 top
NOREF#1443  -  []  333.93 213.57 0 top
NOREF#1444  -  []  50.8 465 0 top
NOREF#1445  -  []  287.59 196.03 0 top
NOREF#1446  -  []  371.05 216.46 90 top
NOREF#1447  -  []  363.33 206.03 0 top
NOREF#1448  -  []  511.37 233.07 0 top
NOREF#1449  -  []  202.61 193.01 0 top
NOREF#1450  -  []  321.8 300.11 0 top
NOREF#1451  -  []  450.62 203.31 0 top
NOREF#1452  -  []  235.49 270.18 90 top
NOREF#1453  -  []  465.73 251.1 0 top
NOREF#1454  -  []  336.8 199 90 top
NOREF#1455  -  []  324.8 195.09 90 top
NOREF#1456  -  []  389.18 196.09 90 top
NOREF#1457  -  []  297.34 204.47 90 top
NOREF#1458  -  []  414.11 83.49 0 top
NOREF#1459  -  []  363.05 255.79 90 top
NOREF#1460  -  []  312.72 381.09 0 top
NOREF#1461  -  []  406.29 238.5 90 top
NOREF#1462  -  []  312.72 375.96 0 top
NOREF#1463  -  []  414.42 267.08 90 top
NOREF#1464  -  []  514.57 273.39 90 top
NOREF#1465  -  []  179.95 296.46 90 top
NOREF#1466  -  []  -9.33 381.27 0 top
NOREF#1467  -  []  226.95 382.58 0 top
NOREF#1468  -  []  288.56 194.22 0 top
NOREF#1469  -  []  286.9 187.37 90 top
NOREF#1470  -  []  332.7 250.29 0 top
NOREF#1471  -  []  521.42 265.14 90 top
NOREF#1472  -  []  50.8 465 0 top
NOREF#1473  -  []  50.8 465 0 top
NOREF#1474  -  []  211.84 184.61 0 top
NOREF#1475  -  []  348.88 208.98 0 top
NOREF#1476  -  []  211.84 244.55 0 top
NOREF#1477  -  []  226.24 168.71 0 top
NOREF#1478  -  []  366.57 194.43 90 top
NOREF#1479  -  []  500.02 198.42 0 top
NOREF#1480  -  []  273.33 261.92 0 top
NOREF#1481  -  []  416.14 265.11 0 top
NOREF#1482  -  []  333.13 137.35 0 top
NOREF#1483  -  []  324.75 278.11 90 top
NOREF#1484  -  []  327.28 199.55 90 top
NOREF#1485  -  []  204.81 261.59 0 top
NOREF#1486  -  []  420.87 216.46 90 top
NOREF#1487  -  []  254.87 228.59 90 top
NOREF#1488  -  []  204.81 244.55 0 top
NOREF#1489  -  []  13.59 406.63 0 top
NOREF#1490  -  []  191.18 253.19 0 top
NOREF#1491  -  []  493.99 242.7 0 top
NOREF#1492  -  []  369.42 254.63 0 top
NOREF#1493  -  []  400.37 199.6 0 top
NOREF#1494  -  []  417.34 263.1 90 top
NOREF#1495  -  []  364.8 196.37 0 top
NOREF#1496  -  []  328.92 382.58 90 top
NOREF#1497  -  []  335.42 259.03 90 top
NOREF#1498  -  []  332.53 153.19 0 top
NOREF#1499  -  []  256.93 281.02 90 top
NOREF#1500  -  []  368.09 195.99 0 top
NOREF#1501  -  []  445.07 291.85 0 top
NOREF#1502  -  []  515.59 373.84 0 top
NOREF#1503  -  []  363.77 150.74 90 top
NOREF#1504  -  []  429.34 183.1 0 top
NOREF#1505  -  []  416.44 263.42 0 top
NOREF#1506  -  []  326.57 195.72 0 top
NOREF#1507  -  []  402.3 256.5 0 top
NOREF#1508  -  []  361.57 258.96 90 top
NOREF#1509  -  []  275.48 254.44 90 top
NOREF#1510  -  []  421.41 172.91 90 top
NOREF#1511  -  []  224.59 174.57 0 top
NOREF#1512  -  []  364.53 263.69 90 top
NOREF#1513  -  []  384.41 138.01 0 top
NOREF#1514  -  []  642.77 1.56 90 top
NOREF#1515  -  []  389.3 186 90 top
NOREF#1516  -  []  202.61 261.59 0 top
NOREF#1517  -  []  328.3 265 0 top
NOREF#1518  -  []  285.97 193.75 0 top
NOREF#1519  -  []  239.54 264.79 0 top
NOREF#1520  -  []  418.68 82.22 90 top
NOREF#1521  -  []  239.54 196.21 0 top
NOREF#1522  -  []  439.67 288.65 90 top
NOREF#1523  -  []  381.41 170.34 90 top
NOREF#1524  -  []  274.08 260.75 0 top
NOREF#1525  -  []  363.61 132.35 90 top
NOREF#1526  -  []  302.85 186 45 top
NOREF#1527  -  []  314.98 82 90 top
NOREF#1528  -  []  175.18 290.8 0 top
NOREF#1529  -  []  326.9 256.05 90 top
NOREF#1530  -  []  331.81 297.41 90 top
NOREF#1531  -  []  292.9 173.55 90 top
NOREF#1532  -  []  328.5 210.01 0 top
NOREF#1533  -  []  226.24 271.58 0 top
NOREF#1534  -  []  352.91 75.38 90 top
NOREF#1535  -  []  332.72 205.56 0 top
NOREF#1536  -  []  393.3 290 0 top
NOREF#1537  -  []  406.13 245.02 0 top
NOREF#1538  -  []  317.89 132.35 90 top
NOREF#1539  -  []  289.87 196.73 0 top
NOREF#1540  -  []  327.08 257.69 0 top
NOREF#1541  -  []  210.19 235.89 0 top
NOREF#1542  -  []  324.57 256.05 90 top
NOREF#1543  -  []  336.84 174.18 0 top
NOREF#1544  -  []  505.92 176.73 0 top
NOREF#1545  -  []  405.68 195.34 90 top
NOREF#1546  -  []  325.68 195.34 90 top
NOREF#1547  -  []  285.7 244.32 90 top
NOREF#1548  -  []  372.17 249.51 90 top
NOREF#1549  -  []  332.33 264.49 0 top
NOREF#1550  -  []  326.87 194.07 0 top
NOREF#1551  -  []  380.87 216.46 90 top
NOREF#1552  -  []  339.69 97.07 90 top
NOREF#1553  -  []  343.83 75.38 0 top
NOREF#1554  -  []  505.73 367.16 90 top
NOREF#1555  -  []  505.92 233.88 0 top
NOREF#1556  -  []  284.1 199 90 top
NOREF#1557  -  []  503.22 225.45 0 top
NOREF#1558  -  []  408.29 251.82 0 top
NOREF#1559  -  []  443.3 146 90 top
NOREF#1560  -  []  410.67 191.75 90 top
NOREF#1561  -  []  325.7 196.05 0 top
NOREF#1562  -  []  386.68 208.98 0 top
NOREF#1563  -  []  253.73 205.43 0 top
NOREF#1564  -  []  232.52 191.61 90 top
NOREF#1565  -  []  385.74 305.15 0 top
NOREF#1566  -  []  333.42 69.49 0 top
NOREF#1567  -  []  288.24 298.51 90 top
NOREF#1568  -  []  368.09 260.49 90 top
NOREF#1569  -  []  300.3 257 90 top
NOREF#1570  -  []  29.14 361.32 0 top
NOREF#1571  -  []  500.02 229.51 90 top
NOREF#1572  -  []  368.88 199.55 90 top
NOREF#1573  -  []  280.3 293 0 top
NOREF#1574  -  []  476.47 373.84 0 top
NOREF#1575  -  []  214.37 296.77 0 top
NOREF#1576  -  []  293.28 209.37 90 top
NOREF#1577  -  []  511.37 187.35 0 top
NOREF#1578  -  []  520.17 186.56 90 top
NOREF#1579  -  []  445.07 264.57 0 top
NOREF#1580  -  []  247.68 218.05 0 top
NOREF#1581  -  []  459.82 225.68 90 top
NOREF#1582  -  []  321.24 142.02 90 top
NOREF#1583  -  []  476.11 98.95 0 top
NOREF#1584  -  []  332.08 270.01 0 top
NOREF#1585  -  []  323.05 195.79 90 top
NOREF#1586  -  []  409.82 186.49 0 top
NOREF#1587  -  []  517.92 181.95 0 top
NOREF#1588  -  []  502.07 241.61 90 top
NOREF#1589  -  []  453.25 211.12 90 top
NOREF#1590  -  []  284.8 247.74 90 top
NOREF#1591  -  []  411.55 189.53 90 top
NOREF#1592  -  []  52.77 405.06 0 top
NOREF#1593  -  []  411.93 102.82 0 top
NOREF#1594  -  []  194.53 225.86 90 top
NOREF#1595  -  []  224.59 270.18 0 top
NOREF#1596  -  []  285.7 196.69 0 top
NOREF#1597  -  []  323.37 196.69 0 top
NOREF#1598  -  []  283.98 259.6 90 top
NOREF#1599  -  []  216.24 244.55 0 top
NOREF#1600  -  []  465.96 301.29 0 top
NOREF#1601  -  []  403.98 199.6 90 top
NOREF#1602  -  []  404.75 288.95 90 top
NOREF#1603  -  []  413.32 197.12 0 top
NOREF#1604  -  []  403.63 204.65 0 top
NOREF#1605  -  []  471.13 276.99 0 top
NOREF#1606  -  []  258.58 238.32 90 top
NOREF#1607  -  []  477.74 278.39 0 top
NOREF#1608  -  []  377.34 204.47 90 top
NOREF#1609  -  []  406.51 167.49 90 top
NOREF#1610  -  []  221.09 277.44 90 top
NOREF#1611  -  []  287.93 244.02 90 top
NOREF#1612  -  []  278.83 207.9 90 top
NOREF#1613  -  []  284.54 212.7 90 top
NOREF#1614  -  []  289.61 199.55 90 top
NOREF#1615  -  []  154.8 45.5 0 top
NOREF#1616  -  []  330.97 250.15 0 top
NOREF#1617  -  []  412.7 250.29 0 top
NOREF#1618  -  []  321.96 361.76 90 top
NOREF#1619  -  []  462.76 267 0 top
NOREF#1620  -  []  468.93 182.52 0 top
NOREF#1621  -  []  198.23 286.08 90 top
NOREF#1622  -  []  368.24 300.71 90 top
NOREF#1623  -  []  209.39 87.9 0 top
NOREF#1624  -  []  473.79 90.26 90 top
NOREF#1625  -  []  462.76 232.71 0 top
NOREF#1626  -  []  405.97 253.75 0 top
NOREF#1627  -  []  288.53 227.49 0 top
NOREF#1628  -  []  310.61 379.8 0 top
NOREF#1629  -  []  296.14 260.99 0 top
NOREF#1630  -  []  410.97 190.15 0 top
NOREF#1631  -  []  251.53 253.74 0 top
NOREF#1632  -  []  328.41 260.19 0 top
NOREF#1633  -  []  491.79 285.39 0 top
NOREF#1634  -  []  284.25 177.55 0 top
NOREF#1635  -  []  316.86 72.06 90 top
NOREF#1636  -  []  369.66 255.8 90 top
NOREF#1637  -  []  412.33 205.91 0 top
NOREF#1638  -  []  477.16 282.2 90 top
NOREF#1639  -  []  407.47 196.04 0 top
NOREF#1640  -  []  445.07 284.84 0 top
NOREF#1641  -  []  423.69 191.08 0 top
NOREF#1642  -  []  454.88 209.81 0 top
NOREF#1643  -  []  328.3 265 0 top
NOREF#1644  -  []  488.28 396.4 0 top
NOREF#1645  -  []  253.73 239.72 0 top
NOREF#1646  -  []  334.22 256.16 90 top
NOREF#1647  -  []  346.14 239.9 90 top
NOREF#1648  -  []  414.22 256.16 90 top
NOREF#1649  -  []  182.03 288.05 90 top
NOREF#1650  -  []  412 84.76 0 top
NOREF#1651  -  []  409.61 259.55 90 top
NOREF#1652  -  []  290.07 252.35 0 top
NOREF#1653  -  []  368.89 251.89 0 top
NOREF#1654  -  []  284.8 256.37 0 top
NOREF#1655  -  []  409.13 191.83 90 top
NOREF#1656  -  []  291.8 261.5 90 top
NOREF#1657  -  []  372.33 204.49 0 top
NOREF#1658  -  []  363.77 133.55 90 top
NOREF#1659  -  []  52.77 405.06 0 top
NOREF#1660  -  []  364.57 256.05 90 top
NOREF#1661  -  []  433.52 225.83 90 top
NOREF#1662  -  []  175.18 210.79 0 top
NOREF#1663  -  []  35.19 391.48 90 top
NOREF#1664  -  []  442.87 188.98 0 top
NOREF#1665  -  []  315.32 296.48 90 top
NOREF#1666  -  []  330.07 245.6 0 top
NOREF#1667  -  []  469.97 106.22 90 top
NOREF#1668  -  []  328.51 256.36 0 top
NOREF#1669  -  []  293.03 196.8 0 top
NOREF#1670  -  []  328.76 269.36 90 top
NOREF#1671  -  []  385.98 203.69 0 top
NOREF#1672  -  []  348.37 147.59 90 top
NOREF#1673  -  []  321.96 361.76 0 top
NOREF#1674  -  []  224.59 277.44 0 top
NOREF#1675  -  []  480.36 225.45 0 top
NOREF#1676  -  []  211.05 382.36 0 top
NOREF#1677  -  []  348.3 235 90 top
NOREF#1678  -  []  482.56 267 0 top
NOREF#1679  -  []  400.37 269.76 0 top
NOREF#1680  -  []  301.41 167.75 90 top
NOREF#1681  -  []  459.65 367.16 90 top
NOREF#1682  -  []  399.47 202.74 0 top
NOREF#1683  -  []  400.3 233 0 top
NOREF#1684  -  []  334.79 75.65 90 top
NOREF#1685  -  []  319.35 228.96 0 top
NOREF#1686  -  []  196.58 278.84 90 top
NOREF#1687  -  []  436.44 227.1 90 top
NOREF#1688  -  []  288.89 251.89 0 top
NOREF#1689  -  []  334.57 278.11 90 top
NOREF#1690  -  []  280.37 202.42 0 top
NOREF#1691  -  []  266.31 226.21 90 top
NOREF#1692  -  []  288.24 295.31 90 top
NOREF#1693  -  []  413.02 197.65 0 top
NOREF#1694  -  []  514.57 204.81 90 top
NOREF#1695  -  []  219.44 168.71 90 top
NOREF#1696  -  []  295.42 199.03 90 top
NOREF#1697  -  []  320.21 171.34 90 top
NOREF#1698  -  []  198.76 270.18 0 top
NOREF#1699  -  []  294.57 282.51 90 top
NOREF#1700  -  []  373.32 200.2 0 top
NOREF#1701  -  []  293.92 204.92 90 top
NOREF#1702  -  []  292.9 171.35 90 top
NOREF#1703  -  []  360.37 262.42 0 top
NOREF#1704  -  []  277.15 288.95 0 top
NOREF#1705  -  []  415.29 244.5 0 top
NOREF#1706  -  []  286.23 247.42 0 top
NOREF#1707  -  []  275.6 277.7 0 top
NOREF#1708  -  []  423.33 235.91 0 top
NOREF#1709  -  []  347.24 77.38 0 top
NOREF#1710  -  []  55.8 0 90 top
NOREF#1711  -  []  222.8 446.5 0 top
NOREF#1712  -  []  508.74 193.82 90 top
NOREF#1713  -  []  324.75 282.51 90 top
NOREF#1714  -  []  459.82 191.39 90 top
NOREF#1715  -  []  284.8 245.52 0 top
NOREF#1716  -  []  421.43 93.57 90 top
NOREF#1717  -  []  204.14 106.86 0 top
NOREF#1718  -  []  439.67 254.36 90 top
NOREF#1719  -  []  403.34 213.34 0 top
NOREF#1720  -  []  187.33 235.89 0 top
NOREF#1721  -  []  330.9 202.85 90 top
NOREF#1722  -  []  286.08 260.19 0 top
NOREF#1723  -  []  359.47 210.08 0 top
NOREF#1724  -  []  404.1 259 0 top
NOREF#1725  -  []  288.67 195.4 90 top
NOREF#1726  -  []  428.82 251.95 0 top
NOREF#1727  -  []  406.48 103.62 0 top
NOREF#1728  -  []  35.49 391.8 0 top
NOREF#1729  -  []  374.58 228.89 0 top
NOREF#1730  -  []  381.41 167.75 90 top
NOREF#1731  -  []  155.68 173.75 0 top
NOREF#1732  -  []  363.33 205.18 0 top
NOREF#1733  -  []  465.96 294.03 0 top
NOREF#1734  -  []  376.24 259.17 0 top
NOREF#1735  -  []  191.18 184.61 0 top
NOREF#1736  -  []  196.58 218.9 90 top
NOREF#1737  -  []  289.31 251.29 90 top
NOREF#1738  -  []  202.61 287.48 0 top
NOREF#1739  -  []  366.58 187.42 0 top
NOREF#1740  -  []  404.2 194.4 0 top
NOREF#1741  -  []  408.5 210.01 0 top
NOREF#1742  -  []  286.99 247.5 90 top
NOREF#1743  -  []  404.48 186.16 0 top
NOREF#1744  -  []  431.62 233.2 0 top
NOREF#1745  -  []  330.18 288.89 0 top
NOREF#1746  -  []  179.95 262.17 90 top
NOREF#1747  -  []  409.86 256.29 0 top
NOREF#1748  -  []  232.16 197.81 0 top
NOREF#1749  -  []  25.88 356.24 90 top
NOREF#1750  -  []  226.93 207.2 90 top
NOREF#1751  -  []  367 187.28 90 top
NOREF#1752  -  []  182.03 208.04 90 top
NOREF#1753  -  []  320.37 259.6 0 top
NOREF#1754  -  []  193.33 258.63 0 top
NOREF#1755  -  []  335.13 212.93 90 top
NOREF#1756  -  []  309.3 186 90 top
NOREF#1757  -  []  218.95 226.92 90 top
NOREF#1758  -  []  290.3 266.6 90 top
NOREF#1759  -  []  324.48 186.16 0 top
NOREF#1760  -  []  313.78 83.52 90 top
NOREF#1761  -  []  367.82 209.36 90 top
NOREF#1762  -  []  520.87 189.54 90 top
NOREF#1763  -  []  233.84 168.71 90 top
NOREF#1764  -  []  372.17 184.64 90 top
NOREF#1765  -  []  509.09 373.44 90 top
NOREF#1766  -  []  496.49 378.53 0 top
NOREF#1767  -  []  402.41 251.74 90 top
NOREF#1768  -  []  368.41 260.19 0 top
NOREF#1769  -  []  283.98 198.4 90 top
NOREF#1770  -  []  408.82 209.11 90 top
NOREF#1771  -  []  405.3 207 90 top
NOREF#1772  -  []  217.88 99.06 0 top
NOREF#1773  -  []  317.29 377.26 90 top
NOREF#1774  -  []  372.17 189.51 90 top
NOREF#1775  -  []  374.22 200.52 0 top
NOREF#1776  -  []  413.34 191.84 0 top
NOREF#1777  -  []  364.75 280.31 90 top
NOREF#1778  -  []  365.7 248.01 0 top
NOREF#1779  -  []  418.69 298.84 90 top
NOREF#1780  -  []  438.34 354.59 0 top
NOREF#1781  -  []  381.41 167.75 90 top
NOREF#1782  -  []  414.12 294.95 0 top
NOREF#1783  -  []  302.94 73.33 0 top
NOREF#1784  -  []  514.57 287.03 90 top
NOREF#1785  -  []  336.44 200.67 0 top
NOREF#1786  -  []  400.89 191.48 90 top
NOREF#1787  -  []  465.73 170.92 90 top
NOREF#1788  -  []  211.05 382.36 0 top
NOREF#1789  -  []  401.57 258.96 90 top
NOREF#1790  -  []  332.4 269.11 90 top
NOREF#1791  -  []  332.33 263.7 0 top
NOREF#1792  -  []  445 81.48 90 top
NOREF#1793  -  []  489.17 218.21 0 top
NOREF#1794  -  []  283.33 204.33 0 top
NOREF#1795  -  []  331.07 256.08 90 top
NOREF#1796  -  []  195.73 258.63 90 top
NOREF#1797  -  []  410.99 192.65 0 top
NOREF#1798  -  []  202.61 203 0 top
NOREF#1799  -  []  374.43 205.59 90 top
NOREF#1800  -  []  363.01 116.51 90 top
